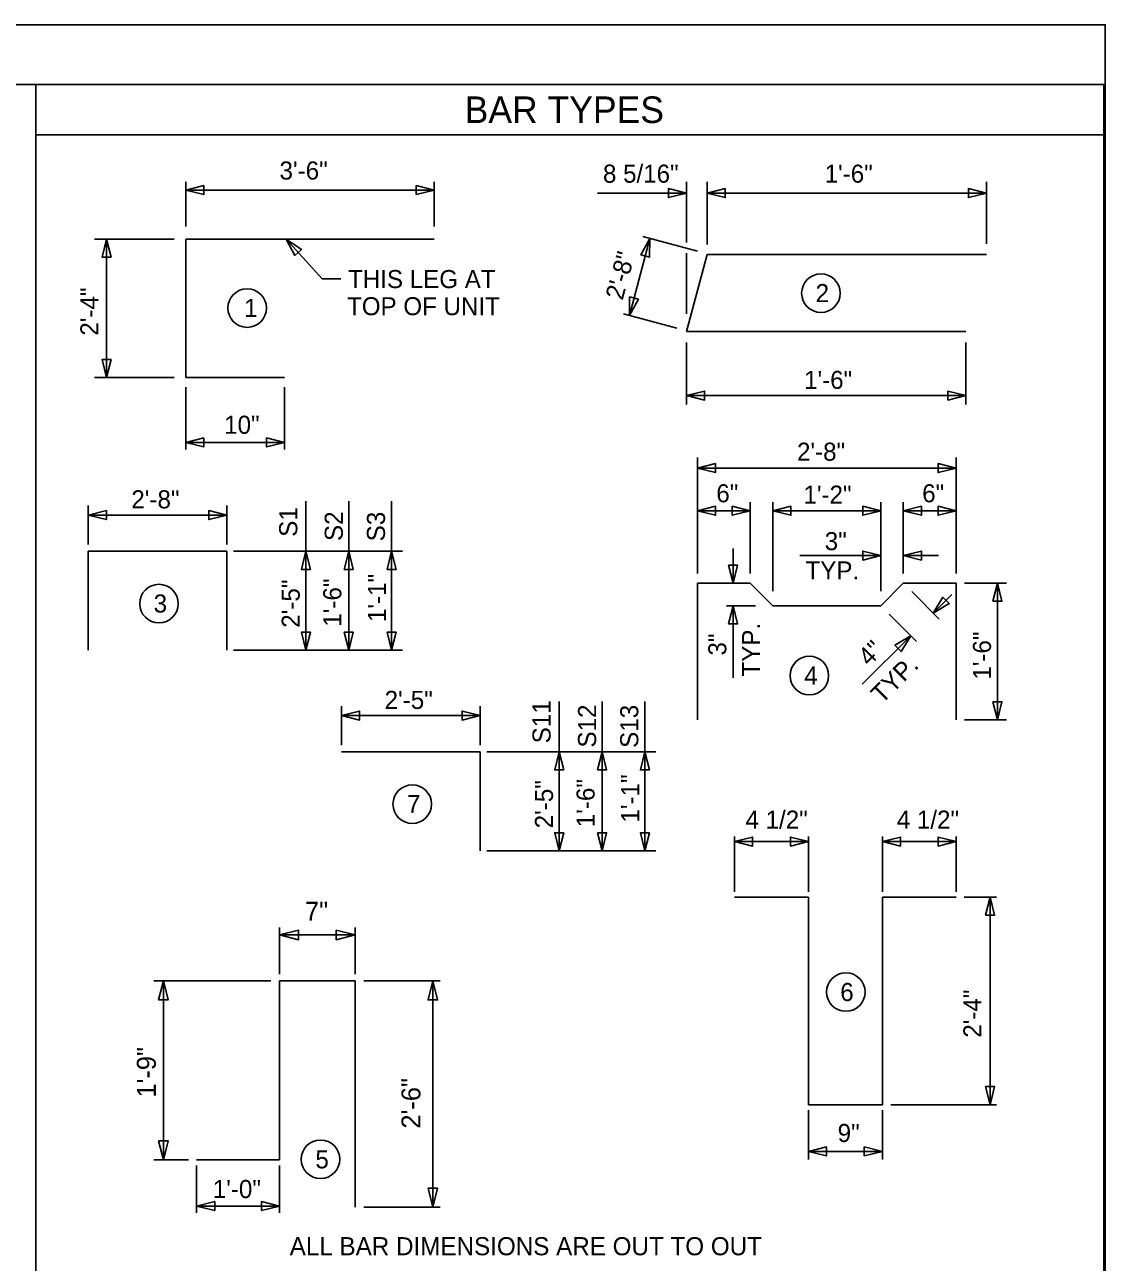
# Model space of a CAD drawing. Extents: x -38 to 94, y -165 to 80.
# Drawn here: x -7.55 to -0.44, y -151.14 to -143 of the extents above; entities that cross this region are included whole.
import ezdxf

# ---------------------------------------------------------------- set-up
doc = ezdxf.new("R2010")
doc.units = 0
for name, color, linetype in [('Arrowhead Terminators', 7, 'Continuous'), ('Arrowhead Terminators CELL', 7, 'Continuous'), ('Dimension Lines', 7, 'Continuous'), ('Plan Sheet', 7, 'Continuous'), ('Plan Sheet CELL', 7, 'Continuous'), ('Plot Shape CELL', 7, 'Continuous'), ('Rebar Lines', 7, 'Continuous'), ('Text', 7, 'Continuous')]:
    doc.layers.add(name, color=color, linetype=linetype)

msp = doc.modelspace()

# ---------------------------------------------------------------- linework, layer by layer
at = {"layer": 'Arrowhead Terminators'}
for points in [[(-6.4874, -144.088), (-6.3687, -144.0583), (-6.3687, -144.1177)], [(-4.8518, -144.088), (-4.9705, -144.1177), (-4.9705, -144.0583)], [(-7.0082, -144.4101), (-6.9785, -144.5289), (-7.0379, -144.5289)], [(-7.0082, -145.3216), (-7.0379, -145.2028), (-6.9785, -145.2028)], [(-6.4874, -145.7488), (-6.3687, -145.7191), (-6.3687, -145.7785)], [(-5.8364, -145.7488), (-5.9551, -145.7785), (-5.9551, -145.7191)], [(-7.1287, -146.2262), (-7.01, -146.2559), (-7.01, -146.1965)], [(-6.2173, -146.2262), (-6.336, -146.1965), (-6.336, -146.2559)], [(-5.6964, -146.4649), (-5.7261, -146.5837), (-5.6667, -146.5837)], [(-5.4142, -146.4649), (-5.4439, -146.5837), (-5.3846, -146.5837)], [(-5.1321, -146.4649), (-5.1618, -146.5837), (-5.1024, -146.5837)], [(-5.6964, -147.116), (-5.6667, -146.9972), (-5.7261, -146.9972)], [(-5.4142, -147.116), (-5.3846, -146.9972), (-5.4439, -146.9972)], [(-5.1321, -147.116), (-5.1024, -146.9972), (-5.1618, -146.9972)], [(-5.4616, -147.546), (-5.3428, -147.5757), (-5.3428, -147.5164)], [(-4.5501, -147.546), (-4.6689, -147.5164), (-4.6689, -147.5757)], [(-4.0293, -147.7847), (-4.0589, -147.9035), (-3.9996, -147.9035)], [(-3.7471, -147.7847), (-3.7768, -147.9035), (-3.7174, -147.9035)], [(-3.465, -147.7847), (-3.4946, -147.9035), (-3.4353, -147.9035)], [(-4.0293, -148.4358), (-3.9996, -148.317), (-4.0589, -148.317)], [(-3.7471, -148.4358), (-3.7174, -148.317), (-3.7768, -148.317)], [(-3.465, -148.4358), (-3.4353, -148.317), (-3.4946, -148.317)], [(-2.8756, -148.375), (-2.7569, -148.4047), (-2.7569, -148.3454)], [(-2.389, -148.375), (-2.5077, -148.3454), (-2.5077, -148.4047)], [(-1.9023, -148.375), (-1.7835, -148.4047), (-1.7835, -148.3454)], [(-1.4156, -148.375), (-1.5344, -148.3454), (-1.5344, -148.4047)], [(-1.1937, -148.741), (-1.2234, -148.8597), (-1.1641, -148.8597)], [(-1.1937, -150.1064), (-1.1641, -149.9877), (-1.2234, -149.9877)], [(-2.389, -150.4139), (-2.2702, -150.3842), (-2.2702, -150.4436)], [(-1.9023, -150.4139), (-2.021, -150.4436), (-2.021, -150.3842)], [(-6.4156, -150.7737), (-6.2969, -150.8034), (-6.2969, -150.744)], [(-5.8696, -150.7737), (-5.9884, -150.744), (-5.9884, -150.8034)]]:
    msp.add_lwpolyline(points, close=True, dxfattribs=at)
at = {"layer": 'Arrowhead Terminators CELL'}
for points in [[(-3.1915, -144.1074), (-3.3103, -144.0777), (-3.3103, -144.1371)], [(-3.0553, -144.1074), (-2.9365, -144.1371), (-2.9365, -144.0777)], [(-1.2169, -144.1074), (-1.3357, -144.0777), (-1.3357, -144.1371)], [(-5.8269, -144.4101), (-5.7693, -144.5181), (-5.7252, -144.4782)], [(-3.4318, -144.4068), (-3.4913, -144.5139), (-3.4339, -144.5292)], [(-3.5676, -144.9136), (-3.5082, -144.8066), (-3.5656, -144.7912)], [(-3.1914, -145.4401), (-3.0727, -145.4698), (-3.0727, -145.4105)], [(-1.3523, -145.4401), (-1.4711, -145.4105), (-1.4711, -145.4698)], [(-3.1197, -145.9175), (-3.0009, -145.9472), (-3.0009, -145.8878)], [(-1.4164, -145.9175), (-1.5351, -145.8878), (-1.5351, -145.9472)], [(-3.1197, -146.1983), (-3.0009, -146.2279), (-3.0009, -146.1686)], [(-2.7717, -146.1983), (-2.8905, -146.1686), (-2.8905, -146.2279)], [(-2.6233, -146.1983), (-2.5045, -146.2279), (-2.5045, -146.1686)], [(-1.9127, -146.1983), (-2.0315, -146.1686), (-2.0315, -146.2279)], [(-1.7643, -146.1983), (-1.6456, -146.1686), (-1.6456, -146.2279)], [(-1.4164, -146.1983), (-1.5351, -146.2279), (-1.5351, -146.1686)], [(-1.9127, -146.4934), (-2.0315, -146.5231), (-2.0315, -146.4637)], [(-1.7643, -146.4934), (-1.6456, -146.4637), (-1.6456, -146.5231)], [(-2.8846, -146.675), (-2.8549, -146.5562), (-2.9143, -146.5562)], [(-1.1447, -146.675), (-1.1744, -146.7937), (-1.115, -146.7937)], [(-2.8846, -146.8234), (-2.9143, -146.9422), (-2.8549, -146.9422)], [(-1.5675, -146.8718), (-1.4625, -146.8089), (-1.5045, -146.7669)], [(-1.7159, -147.0203), (-1.8209, -147.0833), (-1.7789, -147.1252)], [(-1.1447, -147.5734), (-1.115, -147.4547), (-1.1744, -147.4547)], [(-5.8696, -148.9894), (-5.7446, -149.0206), (-5.7446, -148.9581)], [(-5.3723, -148.9894), (-5.4973, -148.9581), (-5.4973, -149.0206)], [(-6.6344, -149.2921), (-6.6657, -149.4171), (-6.6032, -149.4171)], [(-4.8612, -149.2921), (-4.8924, -149.4171), (-4.8299, -149.4171)], [(-6.6344, -150.4692), (-6.6032, -150.3442), (-6.6657, -150.3442)], [(-4.8612, -150.7816), (-4.8299, -150.6566), (-4.8924, -150.6566)]]:
    msp.add_lwpolyline(points, close=True, dxfattribs=at)
at = {"layer": 'Dimension Lines'}
for p, q in [((-6.4874, -144.0337), (-6.4874, -144.3284)), ((-4.8518, -144.0337), (-4.8518, -144.3284)), ((-3.1915, -144.4331), (-3.1915, -144.0338)), ((-3.0553, -144.4457), (-3.0553, -144.0338)), ((-1.2161, -144.4411), (-1.2161, -144.0338)), ((-6.4874, -144.088), (-4.8518, -144.088)), ((-3.1915, -144.1074), (-3.7775, -144.1074)), ((-3.0553, -144.1074), (-1.2169, -144.1074)), ((-6.5645, -144.4101), (-7.089, -144.4101)), ((-7.0082, -144.4101), (-7.0082, -145.3216)), ((-3.5676, -144.9136), (-3.4318, -144.4068)), ((-3.1195, -144.4905), (-3.4786, -144.3943)), ((-3.1915, -144.9032), (-3.1915, -144.5029)), ((-3.607, -144.9031), (-3.2553, -144.9973)), ((-3.1915, -145.091), (-3.1915, -145.4983)), ((-1.3523, -145.091), (-1.3523, -145.4983)), ((-6.5645, -145.3216), (-7.089, -145.3216)), ((-6.4874, -145.3856), (-6.4874, -145.7953)), ((-5.8364, -145.3856), (-5.8364, -145.7953)), ((-3.1914, -145.4401), (-1.3523, -145.4401)), ((-6.4874, -145.7488), (-5.8364, -145.7488)), ((-3.1197, -146.6113), (-3.1197, -145.8486)), ((-1.4164, -146.6113), (-1.4164, -145.8486)), ((-3.1197, -145.9175), (-1.4164, -145.9175)), ((-7.1287, -146.4212), (-7.1287, -146.1641)), ((-6.2173, -146.4212), (-6.2173, -146.1641)), ((-5.6964, -146.1341), (-5.6964, -147.116)), ((-5.4142, -146.1341), (-5.4142, -147.116)), ((-5.1321, -146.1341), (-5.1321, -147.116)), ((-2.7717, -146.1407), (-2.7717, -146.6113)), ((-2.6233, -146.7282), (-2.6233, -146.1407)), ((-1.9127, -146.7282), (-1.9127, -146.1407)), ((-1.7643, -146.1407), (-1.7643, -146.6113)), ((-7.1287, -146.2262), (-6.2173, -146.2262)), ((-5.1321, -146.2045), (-5.1321, -147.116)), ((-2.7717, -146.1983), (-3.1197, -146.1983)), ((-2.6233, -146.1983), (-1.9127, -146.1983)), ((-1.7643, -146.1983), (-1.4164, -146.1983)), ((-6.1735, -146.4649), (-5.0603, -146.4649)), ((-2.8846, -146.675), (-2.8846, -146.4461)), ((-1.9127, -146.4934), (-2.445, -146.4934)), ((-1.7643, -146.4934), (-1.5318, -146.4934)), ((-1.5287, -146.9106), (-1.7088, -146.7305)), ((-1.3606, -146.675), (-1.086, -146.675)), ((-1.1447, -147.5734), (-1.1447, -146.675)), ((-2.7369, -146.8234), (-2.9285, -146.8234)), ((-2.8846, -146.8234), (-2.8846, -147.2975)), ((-1.4442, -146.7486), (-1.5675, -146.8718)), ((-1.6772, -147.059), (-1.8573, -146.8789)), ((-1.7159, -147.0203), (-2.0354, -147.3398)), ((-6.1735, -147.116), (-5.0603, -147.116)), ((-4.0293, -147.4539), (-4.0293, -148.4358)), ((-3.7471, -147.4539), (-3.7471, -148.4358)), ((-3.465, -147.4539), (-3.465, -148.4358)), ((-5.4616, -147.741), (-5.4616, -147.4839)), ((-5.4616, -147.546), (-4.5501, -147.546)), ((-4.5501, -147.741), (-4.5501, -147.4839)), ((-3.465, -147.5243), (-3.465, -148.4358)), ((-1.3606, -147.5734), (-1.086, -147.5734)), ((-4.5063, -147.7847), (-3.3932, -147.7847)), ((-2.8756, -148.7061), (-2.8756, -148.3414)), ((-2.389, -148.7061), (-2.389, -148.3414)), ((-1.9023, -148.7061), (-1.9023, -148.3414)), ((-1.4156, -148.3414), (-1.4156, -148.7061)), ((-4.5063, -148.4358), (-3.3932, -148.4358)), ((-2.8756, -148.375), (-2.389, -148.375)), ((-1.9023, -148.375), (-1.4156, -148.375)), ((-1.3641, -148.741), (-1.1511, -148.741)), ((-1.1937, -148.741), (-1.1937, -150.1064)), ((-5.8696, -149.2484), (-5.8696, -148.9397)), ((-5.3723, -149.2484), (-5.3723, -148.9397)), ((-5.8696, -148.9894), (-5.3723, -148.9894)), ((-5.928, -149.2921), (-6.6972, -149.2921)), ((-6.6344, -149.2921), (-6.6344, -150.4692)), ((-5.3147, -149.2921), (-4.8127, -149.2921)), ((-4.8612, -149.2921), (-4.8612, -150.7816)), ((-2.389, -150.1419), (-2.389, -150.4668)), ((-1.9023, -150.4668), (-1.9023, -150.1419)), ((-1.8469, -150.1064), (-1.1511, -150.1064)), ((-6.4696, -150.4692), (-6.6972, -150.4692)), ((-2.389, -150.4139), (-1.9023, -150.4139)), ((-6.4156, -150.506), (-6.4156, -150.8173)), ((-5.8696, -150.506), (-5.8696, -150.8173)), ((-6.4156, -150.7737), (-5.8696, -150.7737)), ((-5.3147, -150.7816), (-4.8127, -150.7816))]:
    msp.add_line(p, q, dxfattribs=at)
msp.add_lwpolyline([(-5.8269, -144.4101), (-5.5893, -144.6726), (-5.4664, -144.6726)], dxfattribs=at)
at = {"layer": 'Plan Sheet'}
for p, q in [((-7.4749, -157.0238), (-7.4749, -143.3938)), ((-7.4749, -143.7247), (-0.4439, -143.7247))]:
    msp.add_line(p, q, dxfattribs=at)
at = {"layer": 'Plan Sheet CELL'}
for p, q in [((-0.4352, -142.9999), (-0.4352, -142.9999)), ((-32.4443, -143.3938), (-0.4439, -143.3938)), ((-0.4439, -143.3938), (-0.4439, -164.3937))]:
    msp.add_line(p, q, dxfattribs=at)
at = {"layer": 'Plot Shape CELL'}
msp.add_lwpolyline([(-33.4983, -142.9999), (-0.4352, -142.9999), (-0.4352, -164.9999), (-33.4983, -164.9999)], close=True, dxfattribs=at)
at = {"layer": 'Rebar Lines'}
for p, q in [((-4.8518, -144.4101), (-6.4874, -144.4101)), ((-6.4874, -144.4101), (-6.4874, -145.3216)), ((-3.056, -144.5127), (-3.1923, -145.0194)), ((-3.056, -144.5127), (-1.2168, -144.5127)), ((-3.1923, -145.0194), (-1.3531, -145.0194)), ((-6.4874, -145.3216), (-5.8364, -145.3216)), ((-7.1287, -147.116), (-7.1287, -146.4649)), ((-7.1287, -146.4649), (-6.2173, -146.4649)), ((-6.2173, -146.4649), (-6.2173, -147.116)), ((-3.1197, -147.5734), (-3.1197, -146.675)), ((-2.7717, -146.675), (-3.1197, -146.675)), ((-2.6233, -146.8234), (-2.7717, -146.675)), ((-1.9127, -146.8234), (-1.7643, -146.675)), ((-1.7643, -146.675), (-1.4164, -146.675)), ((-1.4164, -147.5734), (-1.4164, -146.675)), ((-2.6233, -146.8234), (-1.9127, -146.8234)), ((-5.4616, -147.7847), (-4.5501, -147.7847)), ((-4.5501, -147.7847), (-4.5501, -148.4358)), ((-2.8756, -148.741), (-2.389, -148.741)), ((-2.389, -150.1064), (-2.389, -148.741)), ((-1.9023, -150.1064), (-1.9023, -148.741)), ((-1.9023, -148.741), (-1.4156, -148.741)), ((-5.8696, -150.4692), (-5.8696, -149.2921)), ((-5.8696, -149.2921), (-5.3723, -149.2921)), ((-5.3723, -150.7816), (-5.3723, -149.2921)), ((-2.389, -150.1064), (-1.9023, -150.1064)), ((-5.8696, -150.4692), (-6.4156, -150.4692))]:
    msp.add_line(p, q, dxfattribs=at)
at = {"layer": 'Text'}
for centre in [(-2.3065, -144.7664), (-6.0833, -144.8643), (-6.6636, -146.809), (-2.3827, -147.2826), (-4.9965, -148.1288), (-2.1424, -149.3651), (-5.6004, -150.4659)]:
    msp.add_circle(centre, 0.127, dxfattribs=at)

# ---------------------------------------------------------------- texts
for s, height, p in [('BAR TYPES', 0.17478, (-4.6515, -143.6465)), ('3\'-6"', 0.11918, (-5.8703, -144.0186)), ('8 5/16"', 0.11875, (-3.7412, -144.0391)), ('1\'-6"', 0.11875, (-2.2819, -144.0391)), ('THIS LEG AT', 0.11875, (-5.4188, -144.7328)), ('2', 0.1192, (-2.3416, -144.8254)), ('1', 0.1192, (-6.1034, -144.9233)), ('TOP OF UNIT', 0.11875, (-5.4258, -144.9114)), ('1\'-6"', 0.11875, (-2.4173, -145.3962)), ('10"', 0.11918, (-6.235, -145.6918)), ('2\'-8"', 0.11875, (-2.4638, -145.8687)), ('2\'-8"', 0.11918, (-6.8457, -146.1825)), ('6"', 0.11875, (-2.9951, -146.1424)), ('1\'-2"', 0.11875, (-2.4213, -146.151)), ('3', 0.1192, (-6.6987, -146.868)), ('4', 0.1192, (-2.4164, -147.3421)), ('2\'-5"', 0.11918, (-5.1786, -147.5023)), ('7', 0.1192, (-5.0316, -148.1878)), ('4 1/2"', 0.11875, (-2.803, -148.2897)), ('4 1/2"', 0.11875, (-1.8072, -148.2897)), ('7"', 0.12521, (-5.7028, -148.8965)), ('6', 0.1192, (-2.1795, -149.4246)), ('9"', 0.11918, (-2.1966, -150.3523)), ('5', 0.1192, (-5.6342, -150.5255)), ('1\'-0"', 0.11918, (-6.3097, -150.721)), ('ALL BAR DIMENSIONS ARE OUT TO OUT', 0.119184, (-5.8032, -151.0974))]:
    msp.add_text(s, height=height, dxfattribs=at).set_placement(p)
for s, height, rotation, p in [('2\'-8"', 0.11875, 74.99928, (-3.612, -144.8177)), ('2\'-4"', 0.11918, 90, (-7.0621, -145.0461)), ('6"', 0.11875, 360, (-1.64, -146.1424)), ('S1', 0.11918, 90, (-5.7531, -146.3695)), ('S2', 0.11918, 90, (-5.4534, -146.3973)), ('S3', 0.11918, 90, (-5.1758, -146.3995)), ('3"', 0.11875, 360, (-2.2813, -146.4575)), ('TYP.', 0.11875, 360, (-2.408, -146.6503)), ('2\'-5"', 0.11918, 90, (-5.7369, -146.9682)), ('1\'-6"', 0.11918, 90, (-5.4634, -146.9611)), ('1\'-1"', 0.11918, 90, (-5.1695, -146.9305)), ('TYP.', 0.11875, 90, (-2.7071, -147.2889)), ('3"', 0.11875, 90, (-2.9294, -147.1509)), ('4"', 0.11875, 45, (-1.9898, -147.227)), ('1\'-6"', 0.11875, 90, (-1.1873, -147.3092)), ('TYP.', 0.11875, 45, (-1.9047, -147.473)), ('S11', 0.11918, 90, (-4.086, -147.7287)), ('S12', 0.11918, 90, (-3.7862, -147.7565)), ('S13', 0.11918, 90, (-3.5087, -147.7587)), ('1\'-1"', 0.11918, 90, (-3.5024, -148.2503)), ('2\'-5"', 0.11918, 90, (-4.0698, -148.288)), ('1\'-6"', 0.11918, 90, (-3.7962, -148.2809)), ('2\'-4"', 0.11875, 90, (-1.2504, -149.6656)), ('1\'-9"', 0.125, 90, (-6.684, -150.0598)), ('2\'-6"', 0.125, 90, (-4.9426, -150.2639))]:
    msp.add_text(s, height=height, rotation=rotation, dxfattribs=at).set_placement(p)

doc.saveas('drawing.dxf')
